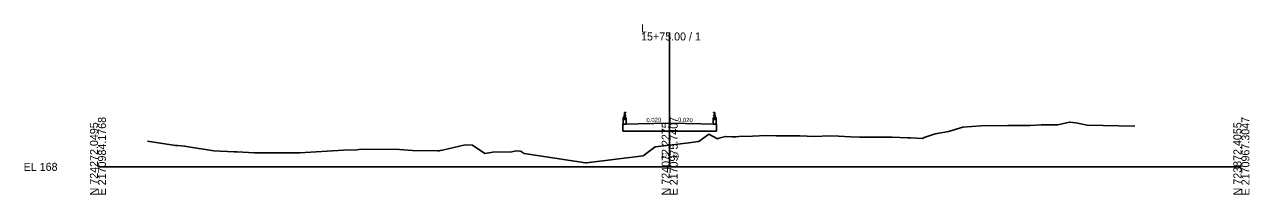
# Model space of a CAD drawing. Extents: x -26 to 2803, y -10 to 9553.
# Drawn here: x -25.7 to 402.8, y 7490.3 to 7549.9 of the extents above; entities that cross this region are included whole.
import ezdxf

# ---------------------------------------------------------------- set-up
doc = ezdxf.new("R2010")
doc.units = 0
for name, color, linetype in [('Exist Cross Section Cell', 7, 'Continuous'), ('Exist XS Center Line Elevation Label', 7, 'Continuous'), ('Exist XS Ground Line', 7, 'Continuous'), ('Prop XS Bridge', 7, 'Continuous'), ('Prop XS Dump Level', 7, 'Continuous'), ('Prop XS SE Text', 7, 'Continuous')]:
    doc.layers.add(name, color=color, linetype=linetype)

msp = doc.modelspace()

# ---------------------------------------------------------------- linework, layer by layer
at = {"layer": 'Exist Cross Section Cell'}
for p, q in [((200, 7500), (200, 7547.06)), ((0, 7500), (200, 7500)), ((200, 7500), (400, 7500))]:
    msp.add_line(p, q, dxfattribs=at)
at = {"layer": 'Exist XS Ground Line'}
msp.add_lwpolyline([(17.39, 7509), (27.1, 7507.48), (27.83, 7507.48), (30.32, 7507.3), (32.43, 7506.94), (40.49, 7505.6), (47.7, 7505.25), (48.73, 7505.21), (54.62, 7504.95), (66.62, 7504.88), (70.61, 7504.92), (85.95, 7505.85), (90.52, 7505.98), (92.22, 7506.16), (105.45, 7506.07), (110.02, 7505.72), (118.75, 7505.6), (119.39, 7505.63), (119.69, 7505.67), (120.58, 7505.87), (128.48, 7507.73), (131, 7507.59), (135.36, 7504.69), (138.17, 7505.13), (144.8, 7505.27), (146.28, 7505.6), (147.65, 7505.5), (148.08, 7505.39), (149.08, 7504.7), (170.57, 7501.4), (170.87, 7501.43), (190.75, 7503.91), (193.99, 7506.27), (194.94, 7507.04), (200, 7507.64), (206.72, 7508.45), (209.1, 7508.73), (209.91, 7508.87), (210.24, 7508.91), (213.7, 7511.44), (216.71, 7509.8), (217.19, 7510.04), (219.48, 7510.64), (221.87, 7510.55), (223.2, 7510.57), (224.24, 7510.59), (229.02, 7510.75), (233.8, 7510.93), (237.24, 7510.84), (242.96, 7510.84), (245.56, 7510.84), (250.68, 7510.59), (255.91, 7510.85), (259.01, 7510.74), (263.43, 7510.56), (266.4, 7510.42), (270.09, 7510.42), (277.81, 7510.4), (283.32, 7510.21), (284.24, 7510.15), (286.52, 7510.01), (288.44, 7509.88), (289.03, 7510.32), (292.89, 7511.57), (297.54, 7512.37), (302.61, 7513.85), (308.8, 7514.31), (318.28, 7514.44), (326.06, 7514.52), (330.01, 7514.7), (335.74, 7514.66), (338.85, 7515.45), (339.96, 7515.69), (342.06, 7515.4), (346.04, 7514.65), (362.73, 7514.28)], dxfattribs=at)
at = {"layer": 'Prop XS Bridge'}
for p, q in [((183.69, 7517.21), (183.73, 7517.25)), ((183.69, 7517.21), (183.69, 7514.98)), ((184.7, 7517.25), (183.73, 7517.25)), ((184.19, 7519.04), (184.07, 7517.33)), ((184.07, 7517.35), (184.07, 7517.38)), ((184.07, 7517.29), (184.07, 7517.33)), ((184.2, 7517.22), (184.11, 7517.22)), ((184.2, 7517.21), (184.11, 7517.21)), ((184.15, 7517.18), (184.11, 7517.18)), ((184.15, 7517.17), (184.11, 7517.17)), ((184.15, 7517.14), (184.11, 7517.14)), ((184.15, 7517.12), (184.11, 7517.12)), ((184.15, 7517.09), (184.11, 7517.09)), ((184.15, 7517.08), (184.11, 7517.08)), ((184.15, 7517.05), (184.11, 7517.05)), ((184.15, 7517.04), (184.11, 7517.04)), ((184.15, 7517.2), (184.13, 7517.2)), ((184.15, 7517.19), (184.13, 7517.19)), ((184.15, 7517.16), (184.13, 7517.16)), ((184.15, 7517.15), (184.13, 7517.15)), ((184.15, 7517.11), (184.13, 7517.11)), ((184.15, 7517.1), (184.13, 7517.1)), ((184.15, 7517.07), (184.13, 7517.07)), ((184.15, 7517.06), (184.13, 7517.06)), ((184.18, 7517.36), (184.14, 7517.36)), ((184.14, 7517.36), (184.14, 7517.33)), ((184.14, 7517.21), (184.14, 7517.29)), ((184.16, 7517.2), (184.15, 7517.2)), ((184.15, 7517.2), (184.15, 7516.69)), ((184.18, 7517.2), (184.16, 7517.2)), ((184.16, 7517.2), (184.16, 7516.69)), ((184.18, 7517.19), (184.16, 7517.19)), ((184.2, 7517.18), (184.16, 7517.18)), ((184.2, 7517.17), (184.16, 7517.17)), ((184.18, 7517.16), (184.16, 7517.16)), ((184.18, 7517.15), (184.16, 7517.15)), ((184.2, 7517.14), (184.16, 7517.14)), ((184.2, 7517.12), (184.16, 7517.12)), ((184.18, 7517.11), (184.16, 7517.11)), ((184.18, 7517.1), (184.16, 7517.1)), ((184.2, 7517.09), (184.16, 7517.09)), ((184.2, 7517.08), (184.16, 7517.08)), ((184.18, 7517.07), (184.16, 7517.07)), ((184.18, 7517.06), (184.16, 7517.06)), ((184.2, 7517.05), (184.16, 7517.05)), ((184.2, 7517.04), (184.16, 7517.04)), ((184.18, 7517.33), (184.18, 7517.36)), ((184.18, 7517.21), (184.18, 7517.29)), ((184.19, 7519.04), (184.3, 7519.08)), ((184.19, 7517.29), (184.19, 7519.04)), ((184.19, 7518.22), (184.19, 7518.22)), ((184.43, 7516.64), (184.21, 7516.64)), ((184.43, 7516.63), (184.21, 7516.63)), ((184.37, 7519.08), (184.3, 7519.08)), ((184.3, 7517.29), (184.3, 7519.08)), ((184.37, 7517.29), (184.37, 7519.08)), ((184.43, 7519.05), (184.43, 7518.95)), ((184.43, 7518.86), (184.43, 7518.95)), ((184.43, 7518.11), (184.43, 7518.02)), ((184.43, 7517.92), (184.43, 7518.02)), ((184.53, 7517.22), (184.44, 7517.22)), ((184.53, 7517.21), (184.44, 7517.21)), ((184.48, 7517.18), (184.44, 7517.18)), ((184.48, 7517.17), (184.44, 7517.17)), ((184.48, 7517.14), (184.44, 7517.14)), ((184.48, 7517.12), (184.44, 7517.12)), ((184.48, 7517.09), (184.44, 7517.09)), ((184.48, 7517.08), (184.44, 7517.08)), ((184.48, 7517.05), (184.44, 7517.05)), ((184.48, 7517.04), (184.44, 7517.04)), ((184.48, 7517.2), (184.46, 7517.2)), ((184.48, 7517.19), (184.46, 7517.19)), ((184.48, 7517.16), (184.46, 7517.16)), ((184.48, 7517.15), (184.46, 7517.15)), ((184.48, 7517.11), (184.46, 7517.11)), ((184.48, 7517.1), (184.46, 7517.1)), ((184.48, 7517.07), (184.46, 7517.07)), ((184.48, 7517.06), (184.46, 7517.06)), ((184.51, 7517.37), (184.47, 7517.37)), ((184.47, 7517.37), (184.47, 7517.34)), ((184.47, 7517.22), (184.47, 7517.3)), ((184.49, 7517.2), (184.48, 7517.2)), ((184.48, 7517.2), (184.48, 7516.69)), ((184.51, 7517.2), (184.49, 7517.2)), ((184.49, 7517.2), (184.49, 7516.69)), ((184.51, 7517.19), (184.49, 7517.19)), ((184.53, 7517.18), (184.49, 7517.18)), ((184.53, 7517.17), (184.49, 7517.17)), ((184.51, 7517.16), (184.49, 7517.16)), ((184.51, 7517.15), (184.49, 7517.15)), ((184.53, 7517.14), (184.49, 7517.14)), ((184.53, 7517.12), (184.49, 7517.12)), ((184.51, 7517.11), (184.49, 7517.11)), ((184.51, 7517.1), (184.49, 7517.1)), ((184.53, 7517.09), (184.49, 7517.09)), ((184.53, 7517.08), (184.49, 7517.08)), ((184.51, 7517.07), (184.49, 7517.07)), ((184.51, 7517.06), (184.49, 7517.06)), ((184.53, 7517.05), (184.49, 7517.05)), ((184.53, 7517.04), (184.49, 7517.04)), ((184.51, 7517.34), (184.51, 7517.37)), ((184.51, 7517.22), (184.51, 7517.3)), ((184.7, 7517.25), (184.75, 7517.21)), ((184.75, 7517.21), (184.75, 7514.98)), ((215.25, 7517.21), (215.3, 7517.25)), ((215.25, 7517.21), (215.25, 7514.98)), ((215.3, 7517.25), (216.27, 7517.25)), ((215.47, 7517.22), (215.56, 7517.22)), ((215.47, 7517.21), (215.56, 7517.21)), ((215.47, 7517.18), (215.51, 7517.18)), ((215.47, 7517.17), (215.51, 7517.17)), ((215.47, 7517.14), (215.51, 7517.14)), ((215.47, 7517.12), (215.51, 7517.12)), ((215.47, 7517.09), (215.51, 7517.09)), ((215.47, 7517.08), (215.51, 7517.08)), ((215.47, 7517.05), (215.51, 7517.05)), ((215.47, 7517.04), (215.51, 7517.04)), ((215.49, 7517.34), (215.49, 7517.37)), ((215.49, 7517.37), (215.53, 7517.37)), ((215.49, 7517.22), (215.49, 7517.3)), ((215.49, 7517.2), (215.51, 7517.2)), ((215.49, 7517.19), (215.51, 7517.19)), ((215.49, 7517.16), (215.51, 7517.16)), ((215.49, 7517.15), (215.51, 7517.15)), ((215.49, 7517.11), (215.51, 7517.11)), ((215.49, 7517.1), (215.51, 7517.1)), ((215.49, 7517.07), (215.51, 7517.07)), ((215.49, 7517.06), (215.51, 7517.06)), ((215.51, 7517.2), (215.52, 7517.2)), ((215.51, 7517.2), (215.51, 7516.69)), ((215.52, 7517.2), (215.54, 7517.2)), ((215.52, 7517.2), (215.52, 7516.69)), ((215.52, 7517.19), (215.54, 7517.19)), ((215.52, 7517.18), (215.56, 7517.18)), ((215.52, 7517.17), (215.56, 7517.17)), ((215.52, 7517.16), (215.54, 7517.16)), ((215.52, 7517.15), (215.54, 7517.15)), ((215.52, 7517.14), (215.56, 7517.14)), ((215.52, 7517.12), (215.56, 7517.12)), ((215.52, 7517.11), (215.54, 7517.11)), ((215.52, 7517.1), (215.54, 7517.1)), ((215.52, 7517.09), (215.56, 7517.09)), ((215.52, 7517.08), (215.56, 7517.08)), ((215.52, 7517.07), (215.54, 7517.07)), ((215.52, 7517.06), (215.54, 7517.06)), ((215.52, 7517.05), (215.56, 7517.05)), ((215.52, 7517.04), (215.56, 7517.04)), ((215.53, 7517.37), (215.53, 7517.34)), ((215.53, 7517.22), (215.53, 7517.3)), ((215.57, 7519.05), (215.57, 7518.95)), ((215.57, 7518.86), (215.57, 7518.95)), ((215.57, 7518.11), (215.57, 7518.02)), ((215.57, 7517.92), (215.57, 7518.02)), ((215.57, 7516.64), (215.79, 7516.64)), ((215.57, 7516.63), (215.79, 7516.63)), ((215.63, 7519.08), (215.7, 7519.08)), ((215.63, 7517.29), (215.63, 7519.08)), ((215.81, 7519.04), (215.7, 7519.08)), ((215.7, 7517.29), (215.7, 7519.08)), ((215.8, 7517.22), (215.89, 7517.22)), ((215.8, 7517.21), (215.89, 7517.21)), ((215.8, 7517.18), (215.84, 7517.18)), ((215.8, 7517.17), (215.84, 7517.17)), ((215.8, 7517.14), (215.84, 7517.14)), ((215.8, 7517.12), (215.84, 7517.12)), ((215.8, 7517.09), (215.84, 7517.09)), ((215.8, 7517.08), (215.84, 7517.08)), ((215.8, 7517.05), (215.84, 7517.05)), ((215.8, 7517.04), (215.84, 7517.04)), ((215.81, 7517.29), (215.81, 7519.04)), ((215.81, 7519.04), (215.93, 7517.33)), ((215.81, 7518.22), (215.81, 7518.22)), ((215.82, 7517.33), (215.82, 7517.36)), ((215.82, 7517.36), (215.86, 7517.36)), ((215.82, 7517.21), (215.82, 7517.29)), ((215.82, 7517.2), (215.84, 7517.2)), ((215.82, 7517.19), (215.84, 7517.19)), ((215.82, 7517.16), (215.84, 7517.16)), ((215.82, 7517.15), (215.84, 7517.15)), ((215.82, 7517.11), (215.84, 7517.11)), ((215.82, 7517.1), (215.84, 7517.1)), ((215.82, 7517.07), (215.84, 7517.07)), ((215.82, 7517.06), (215.84, 7517.06)), ((215.84, 7517.2), (215.85, 7517.2)), ((215.84, 7517.2), (215.84, 7516.69)), ((215.85, 7517.2), (215.87, 7517.2)), ((215.85, 7517.2), (215.85, 7516.69)), ((215.85, 7517.19), (215.87, 7517.19)), ((215.85, 7517.18), (215.89, 7517.18)), ((215.85, 7517.17), (215.89, 7517.17)), ((215.85, 7517.16), (215.87, 7517.16)), ((215.85, 7517.15), (215.87, 7517.15)), ((215.85, 7517.14), (215.89, 7517.14)), ((215.85, 7517.12), (215.89, 7517.12)), ((215.85, 7517.11), (215.87, 7517.11)), ((215.85, 7517.1), (215.87, 7517.1)), ((215.85, 7517.09), (215.89, 7517.09)), ((215.85, 7517.08), (215.89, 7517.08)), ((215.85, 7517.07), (215.87, 7517.07)), ((215.85, 7517.06), (215.87, 7517.06)), ((215.85, 7517.05), (215.89, 7517.05)), ((215.85, 7517.04), (215.89, 7517.04)), ((215.86, 7517.36), (215.86, 7517.33)), ((215.86, 7517.21), (215.86, 7517.29)), ((215.93, 7517.35), (215.93, 7517.38)), ((215.93, 7517.29), (215.93, 7517.33)), ((216.27, 7517.25), (216.31, 7517.21)), ((216.31, 7517.21), (216.31, 7514.98)), ((183.57, 7514.93), (183.62, 7514.98)), ((183.57, 7514.93), (183.57, 7512.48)), ((216.43, 7512.48), (183.57, 7512.48)), ((183.7, 7514.98), (183.62, 7514.98)), ((184.75, 7514.98), (183.7, 7514.98)), ((189, 7515.07), (184.75, 7514.98)), ((189, 7515.07), (200, 7515.29)), ((200, 7515.29), (211, 7515.07)), ((211, 7515.07), (215.25, 7514.98)), ((215.25, 7514.98), (216.3, 7514.98)), ((216.3, 7514.98), (216.38, 7514.98)), ((216.43, 7514.93), (216.38, 7514.98)), ((216.43, 7514.93), (216.43, 7512.48))]:
    msp.add_line(p, q, dxfattribs=at)
for points in [[(184.55, 7517.25), (184.55, 7517.3), (184.39, 7517.3), (184.39, 7517.67), (184.37, 7517.67), (184.37, 7517.29), (184.07, 7517.29), (184.07, 7517.32), (184.07, 7517.32), (184.07, 7517.25), (184.21, 7517.25), (184.21, 7517.28), (184.35, 7517.28), (184.35, 7517.25), (184.55, 7517.25)], [(184.11, 7517.22), (184.11, 7517.21), (184.13, 7517.2), (184.13, 7517.19), (184.11, 7517.18), (184.11, 7517.17), (184.13, 7517.16), (184.13, 7517.15), (184.11, 7517.14), (184.11, 7517.12), (184.13, 7517.11), (184.13, 7517.1), (184.11, 7517.09), (184.11, 7517.08), (184.13, 7517.07), (184.13, 7517.06), (184.11, 7517.05), (184.11, 7517.04)], [(184.2, 7517.29), (184.2, 7517.3), (184.16, 7517.3), (184.12, 7517.3), (184.12, 7517.29)], [(184.19, 7517.3), (184.19, 7517.32), (184.18, 7517.33), (184.13, 7517.33), (184.13, 7517.32), (184.13, 7517.3), (184.19, 7517.3), (184.17, 7517.3), (184.17, 7517.32), (184.17, 7517.33), (184.17, 7517.32), (184.16, 7517.33), (184.15, 7517.33), (184.15, 7517.32), (184.15, 7517.3), (184.15, 7517.32), (184.14, 7517.33)], [(184.2, 7517.22), (184.2, 7517.21), (184.18, 7517.2), (184.18, 7517.19), (184.2, 7517.18), (184.2, 7517.17), (184.18, 7517.16), (184.18, 7517.15), (184.2, 7517.14), (184.2, 7517.12), (184.18, 7517.11), (184.18, 7517.1), (184.2, 7517.09), (184.2, 7517.08), (184.18, 7517.07), (184.18, 7517.06), (184.2, 7517.05), (184.2, 7517.04)], [(184.37, 7518.83), (184.37, 7518.88), (184.39, 7518.88), (184.39, 7518.87), (184.39, 7518.87), (184.39, 7518.85), (184.42, 7518.85), (184.42, 7518.88), (184.42, 7518.95), (184.42, 7519.03), (184.42, 7519.06), (184.39, 7519.06), (184.39, 7519.04), (184.39, 7519.04), (184.39, 7519.03), (184.37, 7519.03), (184.37, 7519.08)], [(184.37, 7517.89), (184.37, 7517.94), (184.39, 7517.94), (184.39, 7517.93), (184.39, 7517.93), (184.39, 7517.91), (184.42, 7517.91), (184.42, 7517.94), (184.42, 7518.02), (184.42, 7518.09), (184.42, 7518.12), (184.39, 7518.12), (184.39, 7518.1), (184.39, 7518.1), (184.39, 7518.09), (184.37, 7518.09), (184.37, 7518.14)], [(184.44, 7517.22), (184.44, 7517.21), (184.46, 7517.2), (184.46, 7517.19), (184.44, 7517.18), (184.44, 7517.17), (184.46, 7517.16), (184.46, 7517.15), (184.44, 7517.14), (184.44, 7517.12), (184.46, 7517.11), (184.46, 7517.1), (184.44, 7517.09), (184.44, 7517.08), (184.46, 7517.07), (184.46, 7517.06), (184.44, 7517.05), (184.44, 7517.04)], [(184.53, 7517.3), (184.53, 7517.31), (184.49, 7517.31), (184.45, 7517.31), (184.45, 7517.3)], [(184.52, 7517.31), (184.52, 7517.33), (184.51, 7517.34), (184.46, 7517.34), (184.46, 7517.33), (184.46, 7517.31), (184.52, 7517.31), (184.5, 7517.31), (184.5, 7517.33), (184.5, 7517.34), (184.5, 7517.33), (184.49, 7517.34), (184.48, 7517.34), (184.48, 7517.33), (184.48, 7517.31), (184.48, 7517.33), (184.47, 7517.34)], [(184.53, 7517.22), (184.53, 7517.21), (184.51, 7517.2), (184.51, 7517.19), (184.53, 7517.18), (184.53, 7517.17), (184.51, 7517.16), (184.51, 7517.15), (184.53, 7517.14), (184.53, 7517.12), (184.51, 7517.11), (184.51, 7517.1), (184.53, 7517.09), (184.53, 7517.08), (184.51, 7517.07), (184.51, 7517.06), (184.53, 7517.05), (184.53, 7517.04)], [(215.45, 7517.25), (215.45, 7517.3), (215.61, 7517.3), (215.61, 7517.67), (215.63, 7517.67), (215.63, 7517.29), (215.93, 7517.29), (215.93, 7517.32), (215.93, 7517.32), (215.93, 7517.25), (215.79, 7517.25), (215.79, 7517.28), (215.65, 7517.28), (215.65, 7517.25), (215.45, 7517.25)], [(215.47, 7517.3), (215.47, 7517.31), (215.51, 7517.31), (215.55, 7517.31), (215.55, 7517.3)], [(215.47, 7517.22), (215.47, 7517.21), (215.49, 7517.2), (215.49, 7517.19), (215.47, 7517.18), (215.47, 7517.17), (215.49, 7517.16), (215.49, 7517.15), (215.47, 7517.14), (215.47, 7517.12), (215.49, 7517.11), (215.49, 7517.1), (215.47, 7517.09), (215.47, 7517.08), (215.49, 7517.07), (215.49, 7517.06), (215.47, 7517.05), (215.47, 7517.04)], [(215.48, 7517.31), (215.48, 7517.33), (215.49, 7517.34), (215.54, 7517.34), (215.54, 7517.33), (215.54, 7517.31), (215.48, 7517.31), (215.5, 7517.31), (215.5, 7517.33), (215.5, 7517.34), (215.5, 7517.33), (215.51, 7517.34), (215.52, 7517.34), (215.52, 7517.33), (215.52, 7517.31), (215.52, 7517.33), (215.53, 7517.34)], [(215.56, 7517.22), (215.56, 7517.21), (215.54, 7517.2), (215.54, 7517.19), (215.56, 7517.18), (215.56, 7517.17), (215.54, 7517.16), (215.54, 7517.15), (215.56, 7517.14), (215.56, 7517.12), (215.54, 7517.11), (215.54, 7517.1), (215.56, 7517.09), (215.56, 7517.08), (215.54, 7517.07), (215.54, 7517.06), (215.56, 7517.05), (215.56, 7517.04)], [(215.63, 7518.83), (215.63, 7518.88), (215.61, 7518.88), (215.61, 7518.87), (215.61, 7518.87), (215.61, 7518.85), (215.58, 7518.85), (215.58, 7518.88), (215.58, 7518.95), (215.58, 7519.03), (215.58, 7519.06), (215.61, 7519.06), (215.61, 7519.04), (215.61, 7519.04), (215.61, 7519.03), (215.63, 7519.03), (215.63, 7519.08)], [(215.63, 7517.89), (215.63, 7517.94), (215.61, 7517.94), (215.61, 7517.93), (215.61, 7517.93), (215.61, 7517.91), (215.58, 7517.91), (215.58, 7517.94), (215.58, 7518.02), (215.58, 7518.09), (215.58, 7518.12), (215.61, 7518.12), (215.61, 7518.1), (215.61, 7518.1), (215.61, 7518.09), (215.63, 7518.09), (215.63, 7518.14)], [(215.8, 7517.29), (215.8, 7517.3), (215.84, 7517.3), (215.88, 7517.3), (215.88, 7517.29)], [(215.8, 7517.22), (215.8, 7517.21), (215.82, 7517.2), (215.82, 7517.19), (215.8, 7517.18), (215.8, 7517.17), (215.82, 7517.16), (215.82, 7517.15), (215.8, 7517.14), (215.8, 7517.12), (215.82, 7517.11), (215.82, 7517.1), (215.8, 7517.09), (215.8, 7517.08), (215.82, 7517.07), (215.82, 7517.06), (215.8, 7517.05), (215.8, 7517.04)], [(215.81, 7517.3), (215.81, 7517.32), (215.82, 7517.33), (215.87, 7517.33), (215.87, 7517.32), (215.87, 7517.3), (215.81, 7517.3), (215.83, 7517.3), (215.83, 7517.32), (215.83, 7517.33), (215.83, 7517.32), (215.84, 7517.33), (215.85, 7517.33), (215.85, 7517.32), (215.85, 7517.3), (215.85, 7517.32), (215.86, 7517.33)], [(215.89, 7517.22), (215.89, 7517.21), (215.87, 7517.2), (215.87, 7517.19), (215.89, 7517.18), (215.89, 7517.17), (215.87, 7517.16), (215.87, 7517.15), (215.89, 7517.14), (215.89, 7517.12), (215.87, 7517.11), (215.87, 7517.1), (215.89, 7517.09), (215.89, 7517.08), (215.87, 7517.07), (215.87, 7517.06), (215.89, 7517.05), (215.89, 7517.04)]]:
    msp.add_lwpolyline(points, dxfattribs=at)
for centre in [(184.12, 7517.07), (184.53, 7517.07), (215.47, 7517.07), (215.88, 7517.07)]:
    msp.add_circle(centre, 0.00793, dxfattribs=at)
for centre, radius, start, end in [((184.21, 7516.69), 0.0665, 180, 270), ((184.21, 7516.69), 0.0507, 180, 270), ((184.44, 7519.05), 0.00744, 90, 180), ((184.44, 7518.86), 0.00744, 180, 270), ((184.44, 7518.11), 0.00744, 90, 180), ((184.44, 7517.92), 0.00744, 180, 270), ((184.43, 7516.69), 0.0507, 270, 0), ((184.43, 7516.69), 0.0665, 270, 0), ((215.57, 7516.69), 0.0665, 180, 270), ((215.57, 7516.69), 0.0507, 180, 270), ((215.56, 7519.05), 0.00744, 0, 90), ((215.56, 7518.86), 0.00744, 270, 360), ((215.56, 7518.11), 0.00744, 0, 90), ((215.56, 7517.92), 0.00744, 270, 360), ((215.79, 7516.69), 0.0507, 270, 0), ((215.79, 7516.69), 0.0665, 270, 0)]:
    msp.add_arc(centre, radius, start, end, dxfattribs=at)
for centre, major_axis, ratio, start_param, end_param in [((184.37, 7518.95), (0.318, 0), 0.39036, 6.282787, 7.853967), ((184.37, 7518.95), (0.318, 0), 0.39036, 4.712404, 6.282787), ((184.37, 7518.02), (0.318, 0), 0.39036, 6.282787, 7.853967), ((184.37, 7518.02), (0.318, 0), 0.39036, 4.712404, 6.282787), ((184.44, 7518.95), (0.211, 0), 0.495501, 6.282718, 7.853881), ((184.44, 7518.95), (0.211, 0), 0.495501, 4.712489, 6.282718), ((184.44, 7518.02), (0.211, 0), 0.495501, 6.282718, 7.853881), ((184.44, 7518.02), (0.211, 0), 0.495501, 4.712489, 6.282718), ((215.63, 7518.95), (-0.318, 0), 0.39036, 4.712404, 6.283584), ((215.63, 7518.95), (-0.318, 0), 0.39036, 0.000398, 1.570782), ((215.63, 7518.02), (-0.318, 0), 0.39036, 4.712404, 6.283584), ((215.63, 7518.02), (-0.318, 0), 0.39036, 0.000398, 1.570782), ((215.56, 7518.95), (-0.211, 0), 0.495501, 4.712489, 6.283652), ((215.56, 7518.95), (-0.211, 0), 0.495501, 0.000467, 1.570696), ((215.56, 7518.02), (-0.211, 0), 0.495501, 4.712489, 6.283652), ((215.56, 7518.02), (-0.211, 0), 0.495501, 0.000467, 1.570696)]:
    msp.add_ellipse(centre, major_axis=major_axis, ratio=ratio, start_param=start_param, end_param=end_param, dxfattribs=at)
at = {"layer": 'Prop XS Dump Level'}
for p, q in [((189, 7515.07), (200, 7515.29)), ((200, 7515.29), (211, 7515.07))]:
    msp.add_line(p, q, dxfattribs=at)

# ---------------------------------------------------------------- texts
at = {"layer": 'Exist Cross Section Cell'}
for s, p in [('15+75.00 / 1', (190, 7544.26)), ('L', (190, 7547.06)), ('EL 168', (-26, 7498.6))]:
    msp.add_text(s, height=2.8, dxfattribs=at).set_placement(p)
for s, p in [('E 2170984.1768', (2.8, 7490)), ('E 2170975.7407', (202.8, 7490)), ('E 2170967.3047', (402.8, 7490)), ('N 724272.0495', (0, 7490)), ('N 724072.2275', (200, 7490)), ('N 723872.4055', (400, 7490))]:
    msp.add_text(s, height=2.8, rotation=90, dxfattribs=at).set_placement(p)
at = {"layer": 'Exist XS Center Line Elevation Label'}
msp.add_text('175.64', height=1.5, dxfattribs=at).set_placement((196.97, 7503.14))
at = {"layer": 'Prop XS SE Text'}
for rotation, p in [(1.1458, (191.88, 7515.62)), (358.8542, (202.88, 7515.73))]:
    msp.add_text('0.020', height=1.5, rotation=rotation, dxfattribs=at).set_placement(p)

doc.saveas('drawing.dxf')
